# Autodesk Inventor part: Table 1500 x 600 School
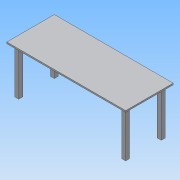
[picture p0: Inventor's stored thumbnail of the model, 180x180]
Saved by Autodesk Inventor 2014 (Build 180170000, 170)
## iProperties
Created: 2013-05
Part Number: Table 1500 x 600 School
Material: Generic
Document SubType Name: Modeling
Designer: john.everitt
Mass: 22910 g
Surface Area: 23446 cm^2
Volume: 22910 cm^3
Density: 1 g/cm^3
Appearance: Default
Author: john.everitt
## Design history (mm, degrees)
sketch "Sketch1"
  geometry: L1 (0, 0)-(1500, 0); L2 (1500, 0)-(1500, 600); L3 (1500, 600)-(0, 600); L4 (0, 600)-(0, 0)
  constraints: 8 end point, 2 parallel, 1 horizontal, 1 perpendicular
  dimensions: "d0" = 1500 distance between parallel lines of L2 L4; "d1" = 600 distance between parallel lines of L3 L1
extrude "Extrusion1" new body sketch "Sketch1" distance "d2" = 19; taper "d3" = 0 deg
sketch "Sketch2"
  geometry: L1 (-1500, 0)-(0, 0) reference; L2 (0, 0)-(0, 600) reference; L3 (0, 600)-(-1500, 600) reference; L4 (-1500, 600)-(-1500, 0) reference; L5 (-1450, 50)-(-50, 50); L6 (-50, 50)-(-50, 550); L7 (-50, 550)-(-1450, 550); L8 (-1450, 550)-(-1450, 50); L9 (-1450, 50)-(-1400, 50); L10 (-1400, 50)-(-1400, 100); L11 (-1400, 100)-(-1450, 100); L12 (-1450, 100)-(-1450, 50); L13 (-1450, 550)-(-1400, 550); L14 (-1400, 550)-(-1400, 500); L15 (-1400, 500)-(-1450, 500); L16 (-1450, 500)-(-1450, 550); L17 (-50, 550)-(-100, 550); L18 (-100, 550)-(-100, 500); L19 (-100, 500)-(-50, 500); L20 (-50, 500)-(-50, 550); L21 (-50, 50)-(-100, 50); L22 (-100, 50)-(-100, 100); L23 (-100, 100)-(-50, 100); L24 (-50, 100)-(-50, 50); 1 further point
  constraints: 40 end point, 8 parallel, 7 equal length, 4 horizontal, 4 perpendicular, 3 other
  dimensions: "d4" = 50 distance between parallel lines of L4 L8; "d5" = 50 distance from line of L10.end L8
extrude "Extrusion2" join sketch "Sketch2" distance "d6" = 581; taper "d7" = 0 deg
body "Solid1"
node "Projected Loop1"
